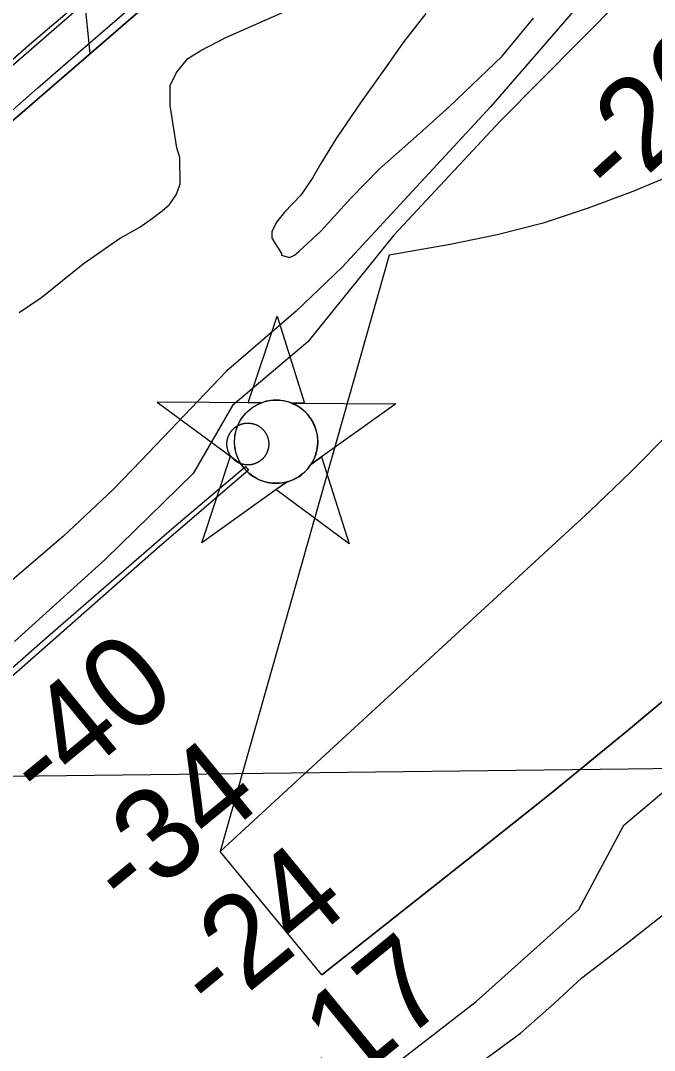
# Model space of a CAD drawing. Extents: x 3704301 to 3742427, y 506229 to 532009.
# Drawn here: x 3712754 to 3713220, y 517556 to 518312 of the extents above; entities that cross this region are included whole.
import ezdxf

# ---------------------------------------------------------------- set-up
doc = ezdxf.new("R2010")
doc.units = 0
for name, color, linetype in [('V-CHAN-DOCK', 7, 'Continuous'), ('V-CHAN-NAID', 7, 'Continuous'), ('V-FLOD-BASE', 7, 'Continuous'), ('V-GRID-MAJR', 7, 'Continuous'), ('V-LEVE-TOET', 7, 'Continuous'), ('V-RIVR-EDGE', 7, 'Continuous'), ('V-RIVR-IDEN', 7, 'Continuous'), ('V-RIVR-RANG', 7, 'Continuous'), ('V-RRAP-FSHR', 7, 'Continuous'), ('V-SITE-VEGE', 7, 'Continuous'), ('V-SURV-LINE', 7, 'Continuous'), ('V-TOPO-DPTH', 7, 'Continuous'), ('V-TOPO-MINR', 7, 'Continuous'), ('V-TRAN-LOCK', 7, 'Continuous')]:
    doc.layers.add(name, color=color, linetype=linetype)

msp = doc.modelspace()

# ---------------------------------------------------------------- linework, layer by layer
at = {"layer": 'V-CHAN-DOCK'}
for points in [[(3712905.94, 518001.12), (3712905.95, 518001.39), (3712905.96, 518001.66), (3712905.98, 518001.92), (3712906, 518002.19), (3712906.03, 518002.46), (3712906.06, 518002.72), (3712906.1, 518002.99), (3712906.14, 518003.25), (3712906.18, 518003.52), (3712906.23, 518003.78), (3712906.29, 518004.04), (3712906.35, 518004.3), (3712906.41, 518004.57), (3712906.48, 518004.83), (3712906.55, 518005.08), (3712906.63, 518005.34), (3712906.71, 518005.6), (3712906.8, 518005.85), (3712906.89, 518006.1), (3712906.98, 518006.35), (3712907.08, 518006.6), (3712907.19, 518006.85), (3712907.29, 518007.09), (3712907.41, 518007.34), (3712907.52, 518007.58), (3712907.64, 518007.82), (3712907.77, 518008.05), (3712907.9, 518008.29), (3712908.03, 518008.52), (3712908.17, 518008.75), (3712908.31, 518008.98), (3712908.45, 518009.21), (3712908.6, 518009.43), (3712908.76, 518009.65), (3712908.91, 518009.86), (3712909.07, 518010.08), (3712909.24, 518010.29), (3712909.4, 518010.5), (3712909.58, 518010.71), (3712909.75, 518010.91), (3712909.93, 518011.11), (3712910.11, 518011.31), (3712910.3, 518011.5), (3712910.48, 518011.69), (3712910.68, 518011.88), (3712910.87, 518012.06), (3712911.07, 518012.24), (3712911.27, 518012.42), (3712911.48, 518012.59), (3712911.69, 518012.76), (3712911.9, 518012.93), (3712912.11, 518013.09), (3712912.32, 518013.25), (3712912.54, 518013.4), (3712912.76, 518013.55), (3712912.99, 518013.7), (3712913.21, 518013.84), (3712913.44, 518013.98), (3712913.68, 518014.12), (3712913.91, 518014.25), (3712914.15, 518014.38), (3712914.38, 518014.5), (3712914.63, 518014.62), (3712914.87, 518014.73), (3712915.11, 518014.84), (3712915.36, 518014.95), (3712915.61, 518015.05), (3712915.86, 518015.15), (3712916.11, 518015.24), (3712916.36, 518015.33), (3712916.62, 518015.41), (3712916.87, 518015.49), (3712917.13, 518015.57), (3712917.39, 518015.63), (3712917.65, 518015.7), (3712917.91, 518015.76), (3712918.17, 518015.82), (3712918.43, 518015.87), (3712918.7, 518015.92), (3712918.96, 518015.96), (3712919.23, 518016), (3712919.49, 518016.03), (3712919.76, 518016.06), (3712920.02, 518016.09), (3712920.29, 518016.11), (3712920.56, 518016.12), (3712920.83, 518016.13), (3712921.1, 518016.14), (3712921.36, 518016.14), (3712921.63, 518016.14), (3712921.9, 518016.13), (3712922.17, 518016.12), (3712922.44, 518016.1), (3712922.7, 518016.08), (3712922.97, 518016.05), (3712923.23, 518016.02), (3712923.5, 518015.98), (3712923.76, 518015.94), (3712924.03, 518015.89), (3712924.29, 518015.85)], [(3712924.29, 518015.85), (3712924.56, 518015.79), (3712924.82, 518015.73), (3712925.08, 518015.67), (3712925.33, 518015.6), (3712925.59, 518015.53), (3712925.85, 518015.45), (3712926.1, 518015.37), (3712926.36, 518015.28), (3712926.61, 518015.19), (3712926.86, 518015.1), (3712927.11, 518015), (3712927.36, 518014.89), (3712927.6, 518014.78), (3712927.85, 518014.67), (3712928.09, 518014.56), (3712928.33, 518014.44), (3712928.56, 518014.31), (3712928.8, 518014.18), (3712929.03, 518014.05), (3712929.26, 518013.91), (3712929.49, 518013.77), (3712929.72, 518013.62), (3712929.94, 518013.48), (3712930.16, 518013.32), (3712930.38, 518013.17), (3712930.59, 518013.01), (3712930.8, 518012.84), (3712931.01, 518012.67), (3712931.22, 518012.5), (3712931.42, 518012.33), (3712931.62, 518012.15), (3712931.82, 518011.97), (3712932.01, 518011.78), (3712932.2, 518011.59), (3712932.39, 518011.4), (3712932.57, 518011.21), (3712932.75, 518011.01), (3712932.93, 518010.81), (3712933.1, 518010.6), (3712933.27, 518010.4), (3712933.44, 518010.18), (3712933.6, 518009.97), (3712933.76, 518009.76), (3712933.91, 518009.54), (3712934.07, 518009.31), (3712934.21, 518009.09), (3712934.35, 518008.86), (3712934.49, 518008.63), (3712934.63, 518008.4), (3712934.76, 518008.17), (3712934.89, 518007.93), (3712935.01, 518007.69), (3712935.13, 518007.46), (3712935.24, 518007.21), (3712935.35, 518006.97), (3712935.46, 518006.72), (3712935.56, 518006.47), (3712935.66, 518006.22), (3712935.75, 518005.97), (3712935.84, 518005.72)], [(3712935.84, 518005.72), (3712935.92, 518005.46), (3712936, 518005.21), (3712936.08, 518004.95), (3712936.15, 518004.69), (3712936.21, 518004.43), (3712936.27, 518004.17), (3712936.33, 518003.91), (3712936.38, 518003.65), (3712936.43, 518003.38), (3712936.47, 518003.12), (3712936.51, 518002.86), (3712936.55, 518002.59), (3712936.57, 518002.32), (3712936.6, 518002.05), (3712936.62, 518001.79), (3712936.63, 518001.52), (3712936.64, 518001.25), (3712936.65, 518000.98), (3712936.65, 518000.72), (3712936.65, 518000.45), (3712936.64, 518000.18), (3712936.63, 517999.91), (3712936.61, 517999.65), (3712936.59, 517999.38), (3712936.56, 517999.11), (3712936.53, 517998.85), (3712936.49, 517998.58), (3712936.45, 517998.31), (3712936.41, 517998.05), (3712936.36, 517997.79), (3712936.3, 517997.52), (3712936.24, 517997.26), (3712936.18, 517997), (3712936.11, 517996.74), (3712936.04, 517996.49), (3712935.96, 517996.23), (3712935.88, 517995.97), (3712935.79, 517995.72), (3712935.7, 517995.47), (3712935.61, 517995.22), (3712935.51, 517994.97), (3712935.41, 517994.72), (3712935.3, 517994.48), (3712935.18, 517994.23), (3712935.07, 517993.99), (3712934.95, 517993.75), (3712934.82, 517993.51), (3712934.69, 517993.28), (3712934.56, 517993.05), (3712934.42, 517992.82), (3712934.28, 517992.59), (3712934.14, 517992.36), (3712933.99, 517992.14), (3712933.84, 517991.92), (3712933.68, 517991.7), (3712933.52, 517991.49), (3712933.35, 517991.28), (3712933.19, 517991.07), (3712933.02, 517990.86), (3712932.84, 517990.66), (3712932.66, 517990.46), (3712932.48, 517990.26), (3712932.29, 517990.07), (3712932.11, 517989.88), (3712931.91, 517989.69), (3712931.72, 517989.51), (3712931.52, 517989.33), (3712931.32, 517989.15), (3712931.11, 517988.98), (3712930.91, 517988.81), (3712930.7, 517988.64), (3712930.48, 517988.48), (3712930.27, 517988.32), (3712930.05, 517988.17), (3712929.83, 517988.02), (3712929.6, 517987.87), (3712929.38, 517987.72), (3712929.15, 517987.59), (3712928.92, 517987.45), (3712928.68, 517987.32), (3712928.45, 517987.19), (3712928.21, 517987.07), (3712927.97, 517986.95), (3712927.72, 517986.84), (3712927.48, 517986.73), (3712927.23, 517986.62), (3712926.99, 517986.52), (3712926.74, 517986.42), (3712926.48, 517986.33), (3712926.23, 517986.24), (3712925.98, 517986.16), (3712925.72, 517986.08), (3712925.46, 517986), (3712925.2, 517985.93), (3712924.94, 517985.87), (3712924.68, 517985.8), (3712924.42, 517985.75), (3712924.16, 517985.7), (3712923.9, 517985.65), (3712923.63, 517985.61)], [(3712923.63, 517985.61), (3712923.37, 517985.57), (3712923.1, 517985.54), (3712922.83, 517985.5), (3712922.57, 517985.48), (3712922.3, 517985.46), (3712922.03, 517985.45), (3712921.76, 517985.43), (3712921.5, 517985.43), (3712921.23, 517985.43), (3712920.96, 517985.43), (3712920.69, 517985.44), (3712920.42, 517985.45), (3712920.16, 517985.47), (3712919.89, 517985.49), (3712919.62, 517985.52), (3712919.36, 517985.55), (3712919.09, 517985.59), (3712918.83, 517985.63), (3712918.56, 517985.67), (3712918.3, 517985.72), (3712918.04, 517985.78), (3712917.78, 517985.84), (3712917.51, 517985.9), (3712917.26, 517985.97), (3712917, 517986.04), (3712916.74, 517986.12), (3712916.49, 517986.2), (3712916.23, 517986.29), (3712915.98, 517986.38), (3712915.73, 517986.47), (3712915.48, 517986.57), (3712915.23, 517986.68), (3712914.99, 517986.78), (3712914.75, 517986.9), (3712914.5, 517987.01), (3712914.26, 517987.13), (3712914.03, 517987.26), (3712913.79, 517987.39), (3712913.56, 517987.52), (3712913.33, 517987.66), (3712913.1, 517987.8), (3712912.88, 517987.94), (3712912.65, 517988.09), (3712912.43, 517988.24), (3712912.21, 517988.4), (3712912, 517988.56), (3712911.79, 517988.73), (3712911.58, 517988.89), (3712911.37, 517989.06), (3712911.17, 517989.24), (3712910.97, 517989.42), (3712910.77, 517989.6), (3712910.58, 517989.79), (3712910.39, 517989.97), (3712910.2, 517990.17), (3712910.02, 517990.36), (3712909.84, 517990.56), (3712909.66, 517990.76), (3712909.49, 517990.97), (3712909.32, 517991.17), (3712909.15, 517991.38), (3712908.99, 517991.6), (3712908.83, 517991.81), (3712908.68, 517992.03), (3712908.53, 517992.25), (3712908.38, 517992.48), (3712908.24, 517992.71), (3712908.1, 517992.93), (3712907.96, 517993.17), (3712907.83, 517993.4), (3712907.71, 517993.64), (3712907.58, 517993.87), (3712907.46, 517994.11), (3712907.35, 517994.36), (3712907.24, 517994.6), (3712907.13, 517994.85), (3712907.03, 517995.1), (3712906.94, 517995.35), (3712906.84, 517995.6), (3712906.75, 517995.85), (3712906.67, 517996.1), (3712906.59, 517996.36), (3712906.52, 517996.62), (3712906.44, 517996.88), (3712906.38, 517997.14), (3712906.32, 517997.4), (3712906.26, 517997.66), (3712906.21, 517997.92), (3712906.16, 517998.18), (3712906.12, 517998.45), (3712906.08, 517998.71), (3712906.04, 517998.98), (3712906.02, 517999.25), (3712905.99, 517999.51), (3712905.97, 517999.78), (3712905.96, 518000.05), (3712905.95, 518000.32), (3712905.94, 518000.58), (3712905.94, 518000.85), (3712905.94, 518001.12)]]:
    msp.add_lwpolyline(points, dxfattribs=at)
at = {"layer": 'V-CHAN-NAID'}
for points in [[(3712931.2, 518030.99), (3712921.61, 518031.06), (3712942.74, 518094.55), (3712962.96, 518030.77), (3712953.37, 518030.84), (3712951.8, 518031.42), (3712949.7, 518032.04), (3712947.66, 518032.49), (3712945.62, 518032.79), (3712944.46, 518032.91), (3712942.92, 518032.99), (3712941.2, 518032.99), (3712939.83, 518032.92), (3712937.93, 518032.72), (3712936.56, 518032.5), (3712934.78, 518032.11), (3712933.25, 518031.69), (3712932.21, 518031.36)], [(3712931.2, 518030.99), (3712854.71, 518031.54), (3712916.27, 517986.14), (3712915.16, 517988.05), (3712914.35, 517989.67), (3712913.52, 517991.64), (3712912.83, 517993.7), (3712912.46, 517995.02), (3712912.1, 517996.65), (3712911.86, 517998.09), (3712911.67, 517999.69), (3712911.56, 518001.42), (3712911.55, 518003.01), (3712911.66, 518005.08), (3712911.84, 518006.7), (3712912.23, 518008.9), (3712912.71, 518010.82), (3712913.31, 518012.71), (3712913.97, 518014.39), (3712914.7, 518015.98), (3712915.51, 518017.51), (3712916.57, 518019.25), (3712917.6, 518020.72), (3712918.6, 518021.99), (3712919.6, 518023.13), (3712920.91, 518024.47), (3712921.96, 518025.44), (3712923.68, 518026.83), (3712924.89, 518027.7), (3712926.58, 518028.77), (3712928.31, 518029.72), (3712929.76, 518030.4)], [(3712953.37, 518030.84), (3713029.87, 518030.29), (3712967.66, 517985.77), (3712968.57, 517987.26), (3712969.55, 517989.11), (3712970.27, 517990.69), (3712971, 517992.65), (3712971.55, 517994.43), (3712971.95, 517996.07), (3712972.31, 517998.08), (3712972.5, 517999.66), (3712972.62, 518001.86), (3712972.59, 518003.92), (3712972.4, 518006.14), (3712972.14, 518007.9), (3712971.64, 518010.13), (3712971, 518012.27), (3712970.25, 518014.26), (3712969.61, 518015.7), (3712968.6, 518017.61), (3712967.54, 518019.34), (3712966.32, 518021.04), (3712965.06, 518022.58), (3712963.79, 518023.94), (3712962.16, 518025.48), (3712960.42, 518026.89), (3712958.73, 518028.06), (3712956.85, 518029.2), (3712955.37, 518029.96)], [(3712949.63, 517972.87), (3712887.43, 517928.34), (3712908.55, 517991.83), (3712916.27, 517986.14), (3712916.91, 517985.17), (3712918.29, 517983.31), (3712919.5, 517981.9), (3712920.97, 517980.4), (3712922.36, 517979.14), (3712923.81, 517977.99), (3712925.21, 517977), (3712926.89, 517975.97), (3712928.61, 517975.05), (3712930.4, 517974.24), (3712931.84, 517973.69), (3712933.47, 517973.16), (3712935.7, 517972.59), (3712937.23, 517972.31), (3712939.25, 517972.05), (3712940.79, 517971.95), (3712942.65, 517971.92), (3712944.34, 517972), (3712946.05, 517972.18), (3712947.95, 517972.49)], [(3712967.66, 517985.77), (3712975.46, 517991.35), (3712995.68, 517927.58), (3712941.83, 517967.29), (3712949.63, 517972.87), (3712951.3, 517973.34), (3712952.91, 517973.9), (3712955.07, 517974.82), (3712956.8, 517975.7), (3712958.67, 517976.81), (3712960.41, 517978.03), (3712961.96, 517979.27), (3712963.25, 517980.44), (3712964.63, 517981.86), (3712965.83, 517983.26), (3712966.95, 517984.73)]]:
    msp.add_lwpolyline(points, close=True, dxfattribs=at)
msp.add_circle((3712942.08, 518002.46), 30.54, dxfattribs=at)
at = {"layer": 'V-FLOD-BASE'}
msp.add_lwpolyline([(3712213.06, 517805.59), (3712216.02, 517810.07), (3712219.16, 517814.42), (3712222.49, 517818.64), (3712225.99, 517822.71), (3712229.66, 517826.63), (3712239.55, 517836.89), (3712249.62, 517846.98), (3712259.84, 517856.91), (3712270.23, 517866.67), (3712280.77, 517876.27), (3712291.47, 517885.69), (3712302.32, 517894.93), (3712313.32, 517904), (3712324.46, 517912.89), (3712386.25, 517968.81), (3712474.93, 518045.13), (3712573.04, 518129.97), (3712667.39, 518211.97), (3712762.67, 518295.39), (3712875.88, 518391.61)], dxfattribs=at)
at = {"layer": 'V-GRID-MAJR'}
msp.add_spline([(3708498.53, 517706.7), (3713778.1, 517769.29), (3719057.66, 517832.65), (3724337.21, 517896.77), (3729616.75, 517961.66), (3734896.28, 518027.32), (3740175.8, 518093.74), (3740175.81, 518093.74)], degree=3, dxfattribs=at)
at = {"layer": 'V-LEVE-TOET'}
msp.add_lwpolyline([(3712737.43, 518236.24), (3712767.07, 518262.18), (3712796.81, 518288), (3712836.23, 518321.99)], dxfattribs=at)
at = {"layer": 'V-RIVR-EDGE'}
for points in [[(3713195.33, 518327.24), (3713106.86, 518238.01), (3713028.61, 518154.16), (3712965.38, 518075.67), (3712910.04, 518028.98), (3712881.1, 517979.22), (3712816.71, 517916.35)], [(3713002.44, 517524.48), (3713089.05, 517591.5), (3713164.26, 517659.15), (3713197.43, 517720.9), (3713229.92, 517748.44), (3713257.57, 517762.18), (3713267.83, 517786.16), (3713286.49, 517806.53), (3713312.34, 517819.07), (3713328.59, 517835.84), (3713334.64, 517853.84), (3713346.08, 517867.01), (3713362.28, 517866.37), (3713378.54, 517884.34), (3713399.57, 517895.1), (3713419.42, 517910.06), (3713438.07, 517926.82), (3713464.55, 517953.77), (3713498.85, 517986.7), (3713555.4, 518031.59), (3713592.67, 518054.91), (3713663.06, 518114.17), (3713740.61, 518159.6)], [(3712816.71, 517916.35), (3712749.92, 517855.88)]]:
    msp.add_lwpolyline(points, dxfattribs=at)
at = {"layer": 'V-RRAP-FSHR'}
msp.add_line((3712805.55, 518287.36), (3712800.59, 518335.94), dxfattribs=at)
for points in [[(3712338.7, 517559.33), (3712311.45, 517564), (3712291.42, 517568.06), (3712270.01, 517575.82), (3712255.89, 517589.45), (3712244.97, 517605.27), (3712231.4, 517635.98), (3712220.99, 517656.96), (3712218.86, 517672.1), (3712217.8, 517682.51), (3712218.08, 517699.35), (3712219.93, 517721.82), (3712224.17, 517740.02), (3712231.45, 517756.78), (3712240.92, 517776.03), (3712252.09, 517792.87), (3712282.45, 517826.16), (3712445.39, 517976.28), (3712728.44, 518220.74), (3713145.32, 518580.93)], [(3712229.15, 517751.49), (3712231.45, 517756.78), (3712240.92, 517776.03), (3712252.09, 517792.87), (3712282.45, 517826.16), (3712445.39, 517976.28), (3712728.44, 518220.74), (3713145.32, 518580.93)], [(3712952.25, 518414.11), (3712728.44, 518220.74), (3712445.39, 517976.28), (3712282.45, 517826.16), (3712252.09, 517792.87), (3712240.92, 517776.03), (3712231.45, 517756.78), (3712224.17, 517740.02), (3712219.93, 517721.82), (3712218.08, 517699.35), (3712217.8, 517682.51), (3712218.86, 517672.1), (3712220.99, 517656.96), (3712231.4, 517635.98), (3712244.97, 517605.27), (3712255.89, 517589.45), (3712270.01, 517575.82), (3712291.42, 517568.06), (3712311.45, 517564), (3712338.7, 517559.33)], [(3712949.08, 518411.38), (3712728.44, 518220.74), (3712445.39, 517976.28), (3712282.45, 517826.16), (3712252.09, 517792.87), (3712240.92, 517776.03), (3712231.45, 517756.78), (3712229.15, 517751.49)]]:
    msp.add_lwpolyline(points, dxfattribs=at)
at = {"layer": 'V-SITE-VEGE'}
for points in [[(3713218.94, 518386.2), (3713099.74, 518248.55), (3712990.61, 518130.55), (3712956.78, 518098.36), (3712905.75, 518054.23), (3712842.87, 517988.67), (3712822.11, 517967.21), (3712785.92, 517933.23), (3712744.97, 517898.04)], [(3712753.42, 518097.28), (3712770.04, 518108.61), (3712800.31, 518133.07), (3712827.02, 518151.56), (3712841.87, 518159.92), (3712851.37, 518166.49), (3712858.49, 518171.86), (3712863.83, 518176.63), (3712868.57, 518183.78), (3712871.53, 518191.51), (3712871.48, 518211.14), (3712869.08, 518218.27), (3712864.25, 518249.18), (3712864.22, 518264.04), (3712868.95, 518273.57), (3712877.25, 518283.7), (3712886.75, 518289.67), (3712905.16, 518299.23), (3712975.26, 518330.32)], [(3713052, 518316.82), (3713035.41, 518295.38), (3713022.96, 518277.51), (3713004.58, 518251.89), (3712986.22, 518225.09), (3712974.96, 518206.63), (3712969.04, 518196.5), (3712960.15, 518183.4), (3712948.29, 518170.88), (3712942.36, 518163.73), (3712938.81, 518156.59), (3712938.82, 518151.83), (3712945.98, 518140.55), (3712945.98, 518139.36), (3712951.93, 518137.59), (3712955.5, 518139.39), (3712959.06, 518142.37), (3712975.08, 518157.27), (3712997.02, 518181.11), (3713017.79, 518202.57), (3713047.46, 518228.8), (3713069.41, 518248.48), (3713107.98, 518285.44), (3713131.1, 518313.44)], [(3713092.97, 517547.43), (3713121.46, 517568.31), (3713146.39, 517590.38), (3713166.56, 517608.86), (3713199.21, 517633.91), (3713234.82, 517661.95)]]:
    msp.add_lwpolyline(points, dxfattribs=at)
at = {"layer": 'V-SURV-LINE'}
msp.add_lwpolyline([(3713323.82, 518778.06), (3712239.75, 517837.28)], dxfattribs=at)
at = {"layer": 'V-TOPO-DPTH'}
msp.add_line((3713024.99, 518139.43), (3712901.02, 517701.61), dxfattribs=at)
for points in [[(3713367.23, 518236.47), (3713543.63, 518085.45), (3713542.9, 518084.78), (3713308.78, 517882.16), (3713254.34, 517835.69), (3713199.47, 517789.74), (3713143.98, 517744.55), (3713088.06, 517699.87), (3712975.59, 517611.27), (3712901.02, 517701.61)], [(3712901.02, 517701.61), (3713172.53, 517951.42), (3713202.38, 517980.08), (3713231.39, 518009.54), (3713259.12, 518040.21), (3713285.99, 518071.68), (3713304.96, 518094.87), (3713320.32, 518116.09), (3713333.87, 518138.28), (3713344.71, 518161.9), (3713353.76, 518186.48), (3713367.37, 518231.59), (3713367.59, 518234.14), (3713367.23, 518236.47)], [(3713230.58, 518197.01), (3713204.13, 518186.09), (3713171.34, 518173.8), (3713138.13, 518162.99), (3713104.28, 518154.38), (3713070, 518147.25), (3713024.99, 518139.43)], [(3712901.02, 517701.61), (3713172.53, 517951.42), (3713202.38, 517980.08), (3713231.39, 518009.54)]]:
    msp.add_lwpolyline(points, dxfattribs=at)
at = {"layer": 'V-TOPO-MINR'}
for points in [[(3713230.58, 518197.01), (3713204.13, 518186.09), (3713171.34, 518173.8), (3713138.13, 518162.99), (3713104.28, 518154.38), (3713070, 518147.25), (3713024.99, 518139.43)], [(3712975.59, 517611.27), (3713088.06, 517699.87), (3713143.98, 517744.55), (3713199.47, 517789.74), (3713254.34, 517835.69), (3713308.78, 517882.16), (3713542.9, 518084.78), (3713543.63, 518085.45)], [(3712901.02, 517701.61), (3713172.53, 517951.42), (3713202.38, 517980.08), (3713231.39, 518009.54)]]:
    msp.add_lwpolyline(points, dxfattribs=at)
at = {"layer": 'V-TRAN-LOCK'}
msp.add_lwpolyline([(3712467.66, 517591.59), (3712511.88, 517631.01), (3712589.99, 517698.74), (3712680.23, 517776.87), (3712774.74, 517859.66), (3712867.12, 517939.94), (3712919.55, 517984.38), (3712921.7, 517981.53), (3712856.08, 517925.26), (3712753.72, 517834.95), (3712658.13, 517752.52), (3712557.19, 517665.42), (3712489.07, 517606.65), (3712470.53, 517588.55), (3712467.66, 517591.59)], dxfattribs=at)

# ---------------------------------------------------------------- texts
at = {"layer": 'V-RIVR-IDEN'}
msp.add_text('ALGIERS CANAL', height=82.9998, rotation=41.17937, dxfattribs=at).set_placement((3712230.74, 517927.2))
at = {"layer": 'V-RIVR-RANG'}
for s, rotation, p in [('-26', 41.86833, (3713191.64, 518176.92)), ('-26', 41.86833, (3713191.64, 518176.92)), ('-40', 39.38833, (3712772.01, 517733.48)), ('-34', 39.38833, (3712833.62, 517654.68)), ('-24', 39.38833, (3712897.69, 517577.89)), ('-17', 39.38833, (3712974.18, 517511.31))]:
    msp.add_text(s, height=67, rotation=rotation, dxfattribs=at).set_placement(p)

doc.saveas('drawing.dxf')
